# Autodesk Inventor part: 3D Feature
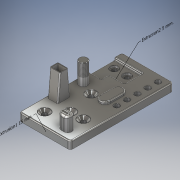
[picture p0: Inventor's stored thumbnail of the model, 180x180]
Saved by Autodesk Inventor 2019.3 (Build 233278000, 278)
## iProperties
Created: 2018-12
Part Number: 3D Feature
Material: Nickel-Copper Alloy 400
Document SubType Name: Modeling
Designer: Karntarat
Density: 8.83 g/cm^3
Appearance: Chrome - Polished
Mass: 1043.79 g
Surface Area: 764.386 cm^2
Volume: 118.21 cm^3
Author: Karntarat
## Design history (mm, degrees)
node "Annotations"
  node "Leader Text 1"
  node "Leader Text 2"
sketch "Sketch1"
  geometry: L1 (0, 0)-(-100, 0); L2 (-100, 0)-(-100, -200); L3 (-100, -200)-(0, -200); L4 (0, -200)-(0, 0)
  constraints: 8 end point, 2 parallel, 1 horizontal, 1 perpendicular
  dimensions: "d0" = 100 distance of L3.end L2.end; "d1" = 200 distance of L2.end L1.end
extrude "Extrusion1" new body sketch "Sketch1" distance "d2" = 15; taper "d3" = 0 deg
sketch "Sketch3"
  geometry: L1 (0, 135)-(25, 135); L2 (25, 135)-(25, 150); L3 (25, 150)-(55, 150); L4 (55, 150)-(55, 185); L5 (55, 185)-(0, 185); L6 (0, 185)-(0, 135); L7 (0, 200)-(0, 0) reference; L8 (100, 200)-(0, 200) reference
  constraints: 12 end point, 4 perpendicular, 2 collinear, 1 horizontal
  dimensions: "d22" = 15 distance between parallel lines of L8 L5; "d23" = 50 distance of L5.end L1.start; "d25" = 25 distance between parallel lines of L6 L2; "d26" = 15 distance from line of L2.end L1; "d27" = 55 distance between parallel lines of L7 L4
extrude "Extrusion2" cut sketch "Sketch3" distance "d28" = 5; taper "d29" = 0 deg
fillet "Fillet1" dims "d30" = 2
fillet "Fillet2" dims "d31" = 2
fillet "Fillet3" dims "d32" = 2
sketch "Sketch2"
  geometry: L1 (0, 200)-(0, 0) reference; L2 (0, 0)-(100, 0) reference; L3 (100, 0)-(100, 200) reference; 4 further points
  dimensions: "d11" = 40 distance from line of L1 point (40, 100); "d12" = 100 distance from line of L2 point (40, 100); "d13" = 50 distance from line of L1 point (50, 50); "d14" = 50 distance from line of L2 point (50, 50); "d15" = 25 distance from line of L1 point (25, 25); "d16" = 25 distance from line of L2 point (25, 25); "d17" = 25 distance from line of L3 point (75, 50); "d18" = 50 distance from line of L2 point (75, 50)
hole "Hole1" sketch "Sketch2" at (40, 100), (50, 50), (25, 25), (75, 50) diameter "d4" = 10; stored, may be unused: countersink angle "d8" = 90 deg, drill point angle "d10" = 118 deg; dims "d5" = 6, "d6" = 20, "d7" = 2, "d9" = 8
sketch "Sketch4"
  geometry: L1 (0, 137)-(0, 183) reference; L2 (100, 200)-(0, 200) reference; 3 further points
  dimensions: "d33" = 15 distance from line of L1 point (15, 170); "d34" = 30 distance from line of L2 point (15, 170); "d35" = 30 distance from line of L2 point (40, 170); "d36" = 40 distance from line of L1 point (40, 170)
hole "Hole2" sketch "Sketch4" at (15, 170), (40, 170) diameter "d37" = 10; stored, may be unused: countersink angle "d41" = 90 deg, drill point angle "d43" = 118 deg; dims "d38" = 6, "d39" = 15, "d40" = 4, "d42" = 8
fillet "Fillet4" dims "d44" = 5
sketch "Sketch5"
  geometry: L1 (95, 200)-(5, 200) reference; L2 (100, 5)-(100, 195) reference; 2 further points
  dimensions: "d45" = 15 distance from line of L1 point (85, 185); "d46" = 15 distance from line of L2 point (85, 185)
hole "Hole3" sketch "Sketch5" at (85, 185) diameter "d47" = 10; stored, may be unused: countersink angle "d51" = 90 deg, drill point angle "d53" = 118 deg; dims "d48" = 6, "d49" = 15, "d50" = 4, "d52" = 8
pattern_linear "Rectangular Pattern1" dims "d56" = 20
sketch "Sketch6"
  geometry: L1 (85, 25)-(65, 25); L2 (65, 25)-(65, 10); L3 (65, 10)-(85, 10); L4 (85, 10)-(85, 25); L5 (100, 5)-(100, 195) reference; L6 (5, 0)-(95, 0) reference; 1 further point
  constraints: 8 end point, 2 parallel, 1 horizontal, 1 perpendicular
  dimensions: "d57" = 15 distance between parallel lines of L5 L4; "d58" = 10 distance between parallel lines of L6 L3; "d59" = 15 distance of L1.end L2.end; "d60" = 20 distance of L1.start L1.end
extrude "Extrusion3" new body sketch "Sketch6" distance "d61" = 30; taper "d62" = 0 deg
fillet "Fillet5"
fillet "Fillet6"
fillet "Fillet7"
fillet "Fillet8" dims "d63" = 5
sketch "Sketch7"
  geometry: L1 (25, 55)-(5, 55); L2 (5, 55)-(5, 75); L3 (5, 75)-(25, 75); L4 (25, 75)-(25, 55); L5 (25, 55)-(5, 75); L6 (5, 55)-(25, 75); 2 further points
  constraints: 12 end point, 2 midpoint, 2 parallel, 1 horizontal, 1 perpendicular
  dimensions: "d64" = 20 distance of L1.start L1.end; "d65" = 5 distance from line of point (0, 0) L2; "d66" = 55 distance from line of L1 point (0, 0); "d67" = 20 distance between parallel lines of L1 L3
extrude "Extrusion4" join sketch "Sketch7" distance "d68" = 50; taper "d69" = 0 deg
feature "FaceDraft1" dims angle "d70" = 5 deg
feature "FaceDraft2" dims angle "d71" = 5 deg
fillet "Fillet9" dims "d72" = 2
sketch "Sketch8"
  geometry: L1 (23, 70.626)-(7, 70.626) reference; L2 (5, 68.618)-(5, 57.008) reference; L3 (7, 55)-(23, 55) reference; L4 (25, 57.008)-(25, 68.618) reference; L5 (23, 69.126)-(7, 69.126); L6 (6.5, 68.618)-(6.5, 57.008); L7 (7, 56.5)-(23, 56.5); L8 (23.5, 57.008)-(23.5, 68.618); 5 further points; 4 other entities
  constraints: 8 end point, 7 parallel, 16 other
  dimensions: "d73" = 1.5 distance between parallel lines of L4 L8
extrude "Extrusion5" cut sketch "Sketch8" distance "d74" = 20; taper "d75" = 0 deg
sketch "Sketch9"
  geometry: L1 (65, 127.5)-(65, 102.5); L2 (75, 127.5)-(75, 102.5); L3 (55, 102.5)-(55, 127.5); A1 r 10 centre (65, 127.5) between (75, 127.5) and (55, 127.5); A2 r 10 centre (65, 102.5) between (55, 102.5) and (75, 102.5); 2 further points
  constraints: 8 end point, 4 point on circle, 4 tangent, 2 centre point, 1 midpoint, 1 parallel, 1 vertical
  dimensions: "d76" = 25 distance of L1.start L1.end; "d77" = 10 radius of A2; "d78" = 115 vertical distance of point (0, 0) point (65, 115); "d79" = 65 horizontal distance of point (0, 0) point (65, 115)
extrude "Extrusion6" join sketch "Sketch9" distance "d80" = 5; taper "d81" = 0 deg
sketch "Sketch10"
  geometry: C1 r 8 at (15, 110); 1 further point
  constraints: 1 centre point
  dimensions: "d83" = 8 radius of C1; "d84" = 110 vertical distance of point (0, 0) C1.centre; "d85" = 15 horizontal distance of C1.centre point (0, 0)
extrude "Extrusion7" new body sketch "Sketch10" distance "d86" = 40; taper "d87" = 0 deg
fillet "Fillet10" dims "d94" = 2
fillet "Fillet11" dims "d95" = 2
thread "Thread1" dims "d88" = 25, "d89" = 0
thread "Thread2" dims "d99" = 10, "d100" = 0
thread "Thread3" dims "d101" = 10, "d102" = 0
chamfer "Chamfer1" distance "d19" = 0.5; stored, may be unused: second distance "d20" = 2, angle "d21" = 45 deg
chamfer "Chamfer2" distance "d90" = 1; stored, may be unused: second distance "d91" = 2, angle "d92" = 45 deg
shell "Shell2" dims "d93" = 3
body "Solid1"
node "Projected Loop1"
body "Solid2"
body "Solid3"
other parameters: "d103" = 5.21151 (derived), "d104" = 6.34588 (derived), "d105" = 5.90476 (derived), "d106" = 3.92327 (derived)
